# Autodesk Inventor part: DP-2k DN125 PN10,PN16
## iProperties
Created: 2009-08
Part Number: DP-2k DN125 PN10,PN16
Document SubType Name: Modelowanie
Designer: Marcin Pyzik
Author: Marcin Pyzik
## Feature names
1. Wyciągnięcie proste1 [Extrusion]
2. Faza1 [Chamfer]
3. Bryła wyprowadzona1 [Tagging]
